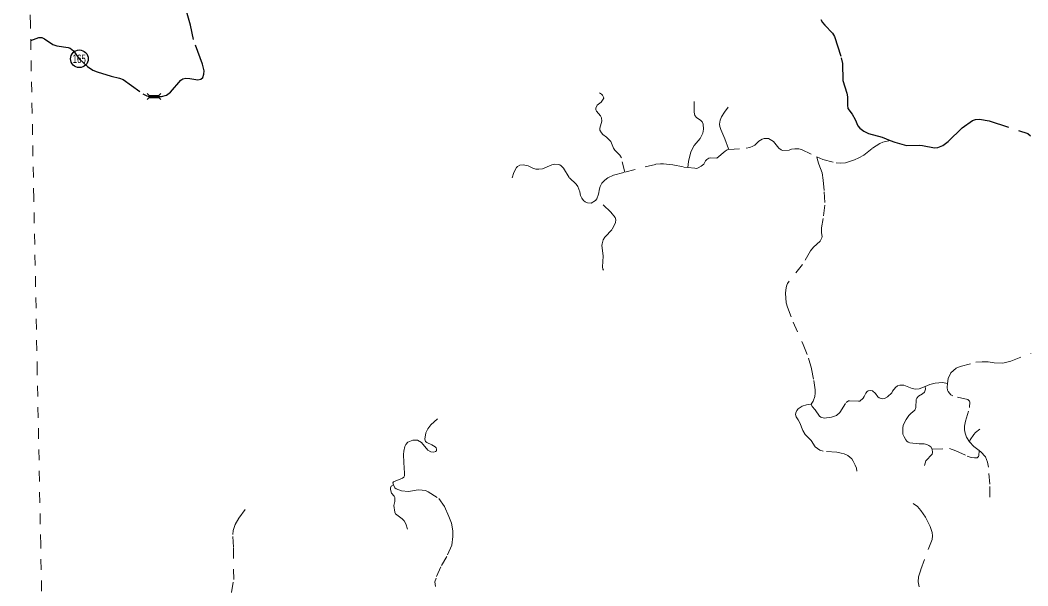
# Model space of a CAD drawing. Extents: x 220.8 to 246.7, y 7287.6 to 7315.8.
# Drawn here: x 220.75 to 230.23, y 7305.15 to 7310.46 of the extents above; entities that cross this region are included whole.
import ezdxf
from ezdxf.enums import TextEntityAlignment as Align

# ---------------------------------------------------------------- set-up
doc = ezdxf.new("R2010")
doc.units = 0
doc.header["$LTSCALE"] = 0.032
for name, pattern in [('DOTTED', [1.5, 0.3, -1.2]), ('LONG_DASHED', [7.5, 6, -1.5]), ('MEDIUM_DASHED', [4.5, 3, -1.5]), ('SHORT_DASHED', [2.7, 1.5, -1.2])]:
    doc.linetypes.add(name, pattern=pattern)
for name, color, linetype, lineweight in [('10', 7, 'Continuous', 25), ('13', 7, 'Continuous', 25), ('35', 7, 'SHORT_DASHED', 13), ('4', 7, 'LONG_DASHED', 25), ('6', 7, 'MEDIUM_DASHED', 13), ('7', 7, 'DOTTED', 13)]:
    doc.layers.add(name, color=color, linetype=linetype, lineweight=lineweight)
doc.layers.add('61', color=7, linetype='Continuous')

msp = doc.modelspace()

# ---------------------------------------------------------------- linework, layer by layer
at = {"layer": '10'}
for p, q in [((221.9666, 7309.7572), (221.9491, 7309.7749)), ((221.9491, 7309.7196), (221.9666, 7309.7372)), ((221.9666, 7309.7372), (222.0591, 7309.7372)), ((222.0768, 7309.7196), (222.0591, 7309.7372))]:
    msp.add_line(p, q, dxfattribs=at)
msp.add_lwpolyline([(221.9666, 7309.7572), (222.0591, 7309.7572), (222.0768, 7309.7749)], dxfattribs=at)
at = {"layer": '13'}
msp.add_circle((221.3114, 7310.1016), 0.083, dxfattribs=at)
at = {"layer": '35'}
msp.add_lwpolyline([(221.3035, 7287.6034), (221.271, 7289.2329), (221.2386, 7290.8624), (221.2062, 7292.4919), (221.1738, 7294.1214), (221.1414, 7295.7509), (221.109, 7297.3804), (221.0767, 7299.0099), (221.0443, 7300.6394), (221.0121, 7302.2689), (220.9798, 7303.8984), (220.9475, 7305.5279), (220.9153, 7307.1574), (220.883, 7308.7869), (220.8508, 7310.4164), (220.8187, 7312.0459), (220.7865, 7313.6754), (220.7543, 7315.3049)], dxfattribs=at)
at = {"layer": '4'}
for points in [[(220.8537, 7310.2749), (220.9299, 7310.3013), (220.9582, 7310.3025), (220.9818, 7310.2895), (221.0631, 7310.2353), (221.0997, 7310.2235), (221.2072, 7310.2076), (221.2255, 7310.2015), (221.2573, 7310.177), (221.3102, 7310.1016), (221.3882, 7310.0278), (221.4371, 7309.9948), (221.4799, 7309.9777), (221.6096, 7309.9385), (221.6903, 7309.919), (221.7245, 7309.9067), (221.908, 7309.7734), (221.9461, 7309.7529), (221.9692, 7309.7476), (222.0832, 7309.7465), (222.1294, 7309.7612), (222.1673, 7309.7893), (222.2651, 7309.9006), (222.2847, 7309.9128), (222.3141, 7309.919), (222.3495, 7309.9165), (222.4254, 7309.9031), (222.4535, 7309.9092), (222.4719, 7309.9263), (222.4829, 7309.9569), (222.4841, 7309.9875), (222.4706, 7310.0511), (222.3838, 7310.2822), (222.3557, 7310.418), (222.3116, 7310.5721)], [(228.2841, 7310.4718), (228.3012, 7310.4425), (228.322, 7310.418), (228.3966, 7310.3434), (228.4149, 7310.3104), (228.4773, 7310.111), (228.4895, 7310.0572), (228.492, 7309.8982), (228.5287, 7309.7771), (228.536, 7309.7441), (228.536, 7309.667), (228.5409, 7309.634), (228.5813, 7309.5814), (228.6082, 7309.5325), (228.6339, 7309.4725), (228.6534, 7309.4481), (228.6914, 7309.4199), (228.7329, 7309.3979), (228.8626, 7309.3637), (228.9364, 7309.3344), (228.98, 7309.3172), (229.0913, 7309.2866), (229.2148, 7309.2891), (229.243, 7309.2866), (229.3555, 7309.2634), (229.3873, 7309.2683), (229.4338, 7309.2878), (229.4827, 7309.3245), (229.616, 7309.4517), (229.7114, 7309.5202), (229.7396, 7309.53), (229.7775, 7309.5349), (229.868, 7309.5178), (230.2325, 7309.3979), (230.2569, 7309.3783)]]:
    msp.add_lwpolyline(points, dxfattribs=at)
at = {"layer": '6'}
for points in [[(225.8441, 7309.0967), (225.8657, 7309.0726), (225.9204, 7308.9823), (225.9851, 7308.9216), (226.0012, 7308.901), (226.0198, 7308.8503), (226.0263, 7308.8172), (226.0373, 7308.7901), (226.0524, 7308.7695), (226.0684, 7308.7569), (226.0895, 7308.7484), (226.1247, 7308.7454), (226.1663, 7308.7685), (226.1798, 7308.785), (226.1949, 7308.8287), (226.2024, 7308.8799), (226.2095, 7308.9025), (226.226, 7308.9331), (226.2536, 7308.9612), (226.2807, 7308.9813), (226.3364, 7309.0069), (226.4407, 7309.0366), (226.7349, 7309.1103), (226.7766, 7309.1158), (226.8042, 7309.1153), (226.8925, 7309.1037), (226.9964, 7309.0837), (227.0338, 7309.0795), (227.1008, 7309.0721), (227.1204, 7309.0716), (227.1304, 7309.0751), (227.1594, 7309.0908), (227.1848, 7309.1117), (227.2013, 7309.1428), (227.2127, 7309.1561), (227.2323, 7309.1675), (227.2494, 7309.17), (227.3084, 7309.1675), (227.387, 7309.2347), (227.4048, 7309.2461), (227.4199, 7309.2504), (227.5817, 7309.2607), (227.6165, 7309.2683), (227.647, 7309.2803), (227.6635, 7309.2905), (227.7021, 7309.3273), (227.7326, 7309.3456), (227.7535, 7309.352), (227.7776, 7309.3539), (227.7941, 7309.3513), (227.8403, 7309.3234), (227.8917, 7309.2619), (227.9114, 7309.2461), (227.9252, 7309.24), (227.9868, 7309.2431), (228.0092, 7309.2508), (228.0415, 7309.2554), (228.077, 7309.2554), (228.1024, 7309.2477), (228.2484, 7309.1816)], [(228.2484, 7309.1816), (228.305, 7309.156), (228.4282, 7309.1229), (228.4721, 7309.1206), (228.5183, 7309.1237), (228.603, 7309.1522), (228.6439, 7309.1699), (228.6893, 7309.1968), (228.771, 7309.2631), (228.841, 7309.3047), (228.868, 7309.317), (228.9364, 7309.3344)], [(228.2484, 7309.1816), (228.2533, 7309.1529), (228.2657, 7309.1121), (228.2965, 7309.0305), (228.3088, 7308.9619), (228.318, 7308.8495), (228.3227, 7308.7262), (228.3088, 7308.6007), (228.2926, 7308.5113), (228.2931, 7308.4653), (228.2973, 7308.4325), (228.2952, 7308.4197), (228.2788, 7308.3881), (228.2162, 7308.3296), (228.1876, 7308.2952), (228.1124, 7308.1678), (227.9722, 7307.9891), (227.9645, 7307.9729), (227.9599, 7307.9506), (227.9545, 7307.8997), (227.9607, 7307.8089), (227.973, 7307.768), (228.0261, 7307.6255), (228.1193, 7307.4145), (228.1686, 7307.2874), (228.1979, 7307.1865), (228.2195, 7307.0771), (228.2325, 7306.9909), (228.2333, 7306.9577), (228.2287, 7306.9277), (228.2135, 7306.8823)], [(229.875, 7305.9804), (229.8743, 7306.1039), (229.8614, 7306.2633), (229.8533, 7306.3107), (229.8357, 7306.3596), (229.7916, 7306.4057), (229.7734, 7306.4183), (229.7251, 7306.4566), (229.6824, 7306.5013), (229.6566, 7306.5434), (229.6431, 7306.5834), (229.6376, 7306.6126), (229.6376, 7306.6465), (229.6451, 7306.6939), (229.6831, 7306.8228), (229.6878, 7306.8757), (229.6837, 7306.8845), (229.6668, 7306.8988), (229.5257, 7306.932), (229.5074, 7306.9422), (229.4823, 7306.9727), (229.4776, 7306.9869), (229.4742, 7307.0114), (229.4755, 7307.0496), (229.4837, 7307.0968), (229.5067, 7307.1497), (229.5569, 7307.1918), (229.5956, 7307.2094), (229.7441, 7307.2494), (229.8031, 7307.2528), (229.8587, 7307.2515), (229.9157, 7307.2433), (229.9984, 7307.2399), (230.0737, 7307.2596), (230.2623, 7307.3335)], [(224.6794, 7306.7184), (224.6187, 7306.6612), (224.5881, 7306.6238), (224.5701, 7306.5857), (224.5619, 7306.5252), (224.5671, 7306.505), (224.5794, 7306.4936), (224.6262, 7306.4736), (224.6576, 7306.455), (224.6673, 7306.4438), (224.671, 7306.4303), (224.669, 7306.4173), (224.6607, 7306.4085), (224.6439, 7306.4042), (224.618, 7306.4079), (224.5899, 7306.423), (224.5283, 7306.4931), (224.4924, 7306.5162), (224.4483, 7306.5177), (224.3997, 7306.4961), (224.3811, 7306.4744), (224.3721, 7306.4565), (224.3631, 7306.4131), (224.3601, 7306.3817), (224.3624, 7306.3063), (224.3706, 7306.2046), (224.3691, 7306.1807), (224.3639, 7306.1687), (224.3512, 7306.1575), (224.266, 7306.1239), (224.2607, 7306.1157), (224.2652, 7306.097), (224.2794, 7306.0686), (224.2899, 7306.0574), (224.3415, 7306.041), (224.4057, 7306.035), (224.4976, 7306.0486), (224.5365, 7306.0469), (224.5666, 7306.0417), (224.5922, 7306.0314), (224.6927, 7305.967), (224.7472, 7305.8915), (224.7868, 7305.7996), (224.8122, 7305.7346), (224.8227, 7305.6651), (224.8235, 7305.6113), (224.8137, 7305.5306), (224.7682, 7305.4237), (224.7106, 7305.3251), (224.6658, 7305.2197), (224.6561, 7305.1853), (224.6611, 7305.1414)], [(222.743, 7305.0834), (222.7627, 7305.2048), (222.7608, 7305.5096), (222.7533, 7305.63), (222.7589, 7305.6667), (222.7759, 7305.7222), (222.8107, 7305.7843), (222.8761, 7305.8713)]]:
    msp.add_lwpolyline(points, dxfattribs=at)
at = {"layer": '7'}
msp.add_line((228.1941, 7306.8542), (228.2135, 7306.8823), dxfattribs=at)
for points in [[(226.4407, 7309.0366), (226.4097, 7309.1705), (226.3944, 7309.1951), (226.3482, 7309.2429), (226.3354, 7309.2606), (226.3088, 7309.3231), (226.296, 7309.3403), (226.2704, 7309.3649), (226.2355, 7309.3915), (226.2212, 7309.4067), (226.2074, 7309.4308), (226.2055, 7309.4481), (226.2252, 7309.5145), (226.2227, 7309.547), (226.2124, 7309.5667), (226.176, 7309.6109), (226.17, 7309.6223), (226.1691, 7309.639), (226.1809, 7309.6656), (226.2207, 7309.6936), (226.2434, 7309.7305), (226.2419, 7309.7423), (226.2316, 7309.7596), (226.2227, 7309.7704), (226.205, 7309.7832)], [(227.0929, 7309.6993), (227.0954, 7309.5999), (227.1016, 7309.569), (227.1151, 7309.5489), (227.1578, 7309.5218), (227.1681, 7309.5099), (227.178, 7309.4877), (227.1804, 7309.4401), (227.1743, 7309.4039), (227.1513, 7309.3513), (227.0954, 7309.2872), (227.0613, 7309.2268), (227.0408, 7309.1377), (227.0338, 7309.0795)], [(227.4139, 7309.6481), (227.3785, 7309.6015), (227.3503, 7309.5562), (227.3387, 7309.5259), (227.3312, 7309.4865), (227.3344, 7309.4658), (227.3447, 7309.4368), (227.3837, 7309.3497), (227.4199, 7309.2504)], [(225.3819, 7308.9833), (225.398, 7309.034), (225.4241, 7309.0801), (225.4331, 7309.0897), (225.4552, 7309.1007), (225.4853, 7309.1052), (225.5315, 7309.0942), (225.5761, 7309.0736), (225.6052, 7309.0651), (225.6343, 7309.0631), (225.667, 7309.0681), (225.7538, 7309.1052), (225.7809, 7309.1103), (225.8155, 7309.1093), (225.8311, 7309.1052), (225.8441, 7309.0967)], [(226.2397, 7308.1132), (226.2343, 7308.1254), (226.2311, 7308.1458), (226.2374, 7308.2486), (226.2266, 7308.3451), (226.2279, 7308.3614), (226.2392, 7308.3985), (226.2533, 7308.4239), (226.3266, 7308.5031), (226.3538, 7308.5616), (226.3565, 7308.5887), (226.3497, 7308.6096), (226.3108, 7308.6598), (226.1798, 7308.785)], [(229.2668, 7307.0211), (229.3115, 7307.0405), (229.3598, 7307.0537), (229.4313, 7307.0587), (229.4755, 7307.0496)], [(228.1941, 7306.8542), (228.2047, 7306.8328), (228.2336, 7306.801), (228.272, 7306.7427), (228.284, 7306.7332), (228.3175, 7306.7237), (228.3844, 7306.7312), (228.4314, 7306.7493), (228.4632, 7306.7766), (228.5231, 7306.8716), (228.5454, 7306.8848), (228.5541, 7306.886), (228.6412, 7306.8819), (228.6512, 7306.8844), (228.683, 7306.9121), (228.6933, 7306.9261), (228.7077, 7306.9591), (228.7218, 7306.974), (228.7321, 7306.9794), (228.7561, 7306.9839), (228.7709, 7306.9806), (228.7986, 7306.9538), (228.8213, 7306.9236), (228.8341, 7306.9141), (228.8622, 7306.9046), (228.8857, 7306.9079), (228.9138, 7306.924), (228.9518, 7306.9604), (228.9601, 7306.9765), (228.9869, 7307.012), (229.0055, 7307.0265), (229.0274, 7307.0339), (229.067, 7307.0343), (229.1447, 7307.0017), (229.1769, 7306.9955), (229.2116, 7306.9976), (229.2668, 7307.0211)], [(229.2668, 7307.0211), (229.2702, 7306.9947), (229.2595, 7306.967), (229.2426, 7306.9513), (229.2054, 7306.9298), (229.188, 7306.9112), (229.1835, 7306.8988), (229.1785, 7306.8233), (229.1695, 7306.7997), (229.1306, 7306.7663), (229.1141, 7306.7477), (229.0881, 7306.7118), (229.0703, 7306.6762), (229.0608, 7306.6531), (229.058, 7306.6312), (229.0575, 7306.5742), (229.0687, 7306.5466), (229.0856, 7306.5181), (229.0951, 7306.5061), (229.1071, 7306.4974), (229.1236, 7306.4908), (229.2103, 7306.4817), (229.2566, 7306.4805), (229.2839, 7306.4747), (229.302, 7306.4664), (229.3194, 7306.4536), (229.3342, 7306.4305)], [(228.6234, 7306.2254), (228.6198, 7306.2525), (228.6094, 7306.2828), (228.5908, 7306.3194), (228.5755, 7306.342), (228.5597, 7306.3578), (228.5393, 7306.3709), (228.5036, 7306.3867), (228.476, 7306.3944), (228.4372, 7306.4026), (228.3065, 7306.4125), (228.2763, 7306.4211), (228.2333, 7306.4523), (228.1931, 7306.5138), (228.138, 7306.5703), (228.1149, 7306.6087), (228.0887, 7306.6778), (228.0733, 7306.7077), (228.0543, 7306.7348), (228.0485, 7306.7565), (228.0507, 7306.7718), (228.0599, 7306.7937), (228.0708, 7306.8098), (228.1089, 7306.8362), (228.1513, 7306.8479), (228.1941, 7306.8542)], [(229.6824, 7306.5013), (229.6912, 7306.5196), (229.7238, 7306.5692), (229.7414, 7306.5875), (229.7821, 7306.6193)], [(229.3342, 7306.4305), (229.3363, 7306.4008), (229.3318, 7306.3859), (229.2739, 7306.3223), (229.2599, 7306.279)], [(229.3342, 7306.4305), (229.4958, 7306.4364), (229.5546, 7306.4171), (229.6632, 7306.3665), (229.6994, 7306.3542), (229.731, 7306.3492), (229.7553, 7306.3517), (229.7685, 7306.3624), (229.7713, 7306.3698), (229.7734, 7306.4183)], [(224.3986, 7305.6796), (224.3835, 7305.7291), (224.3656, 7305.7572), (224.3476, 7305.7761), (224.2855, 7305.8252), (224.2773, 7305.8387), (224.27, 7305.9023), (224.2773, 7305.9402), (224.2797, 7305.977), (224.2734, 7305.9901), (224.2477, 7306.0183), (224.2394, 7306.0387), (224.2365, 7306.0571), (224.2384, 7306.0697), (224.2452, 7306.0828), (224.2652, 7306.097)], [(229.1541, 7305.9209), (229.1944, 7305.8935), (229.2261, 7305.855), (229.2688, 7305.7916), (229.3152, 7305.7031), (229.3329, 7305.6494), (229.3365, 7305.6159), (229.3316, 7305.5817), (229.2249, 7305.2968), (229.2041, 7305.2322), (229.1999, 7305.184), (229.2108, 7305.1388)]]:
    msp.add_lwpolyline(points, dxfattribs=at)

# ---------------------------------------------------------------- texts
at = {"layer": '61', "width": 0.7}
msp.add_text('165', height=0.08, dxfattribs=at).set_placement((221.3101, 7310.0616), align=Align.CENTER)

doc.saveas('drawing.dxf')
